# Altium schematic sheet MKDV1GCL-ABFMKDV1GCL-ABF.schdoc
size 127 x 101 mm
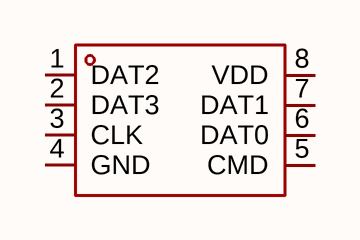
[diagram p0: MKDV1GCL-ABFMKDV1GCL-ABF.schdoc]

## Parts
U?  mkdv1gcl-abf  [LGA-8_L8.0-W6.0-P1.27-TL_MKDV1GCL-ABF]  (value not drawn)

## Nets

Not connected (* = marked no-connect by the designer): U? 1(DAT2) 2(DAT3) 3(CLK) 4(GND) 5(CMD) 6(DAT0) 7(DAT1) 8(VDD)

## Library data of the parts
U? = mkdv1gcl-abf: 存储容量:1Gbit;时钟频率(fc):50MHz;工作电压:2.7V~3.6V;; Manufacturer: MK(米客方德); AddInBom: yes; Memory Size: 1Gbit; Interface: SD接口; Clock Frequency: 50MHz; Data Retention - TDR (Year): 10年; Standby Supply Current: 80uA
